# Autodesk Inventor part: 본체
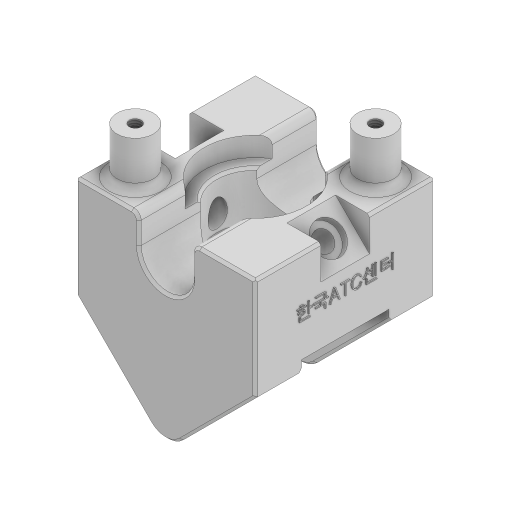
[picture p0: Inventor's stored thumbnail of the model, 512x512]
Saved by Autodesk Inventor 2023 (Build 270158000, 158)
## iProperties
Created: 2025-02
Part Number: 본체
Material: 일반
Document SubType Name: Modeling
Designer: home
Density: 1 g/cm^3
Appearance: 기본값
Author: home
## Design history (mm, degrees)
sketch "스케치1"
  geometry: L1 (-37, 21)-(37, 21); L2 (37, 21)-(37, -21); L3 (-37, -21)-(-37, 21); L4 (-37, 21)-(37, -21); L5 (37, 21)-(-37, -21); L6 (-37, -21)-(0, -58); L7 (0, -58)-(37, -21); 1 further point
  constraints: 14 end point, 2 midpoint, 1 horizontal, 1 parallel, 1 perpendicular, 1 vertical alignment
  dimensions: "d0" = 74 distance of L1.start L1.end; "d2" = 90 deg angle of L7 L6; "d3" = 42 distance of L1.end L2.end
extrude "돌출1" new body sketch "스케치1" stored distance "d4" = 74; taper "d5" = 0 deg
sketch "스케치2"
  geometry: C1 r 21 at (37, 37); C2 r 16 at (37, 37); 1 further point
  constraints: 2 centre point, 2 coincident
  dimensions: "d6" = 42 diameter of C1; "d8" = 32 diameter of C2
extrude "돌출2" cut sketch "스케치2" distance "d9" = 28; taper "d10" = 0 deg
sketch "스케치3"
  geometry: C1 r 16 at (37, 37) reference; C2 r 21 at (37, 37)
  constraints: 1 centre point, 1 coincident
  dimensions: "d11" = 42 diameter of C2
extrude "돌출3" cut sketch "스케치3" distance "d12" = 8; taper "d13" = 0 deg
sketch "스케치4"
  geometry: C1 r 21 at (37, 37) reference; A1 r 7.5 centre (61.749, 61.749) between (66.453, 55.908) and (55.908, 66.453); A2 r 7.5 centre (12.251, 12.251) between (7.547, 18.092) and (18.092, 7.547); A3 r 35 centre (37, 37) between (55.908, 66.453) and (7.547, 18.092); A4 r 35 centre (37, 37) between (18.092, 7.547) and (66.453, 55.908)
  constraints: 8 point on circle, 4 centre point, 1 coincident
  dimensions: "d15" = 15 diameter of A1; "d16" = 15 diameter of A2
extrude "돌출4" join sketch "스케치4" distance "d17" = 19; taper "d18" = 0 deg
sketch "스케치5"
  geometry: L1 (0, -58)-(-37, -21) reference; L2 (-37, -21)-(-37, 21) reference; L3 (-37, 21)-(-21, 21) reference; L4 (-21, 21)-(-21, 13) reference; L5 (-21, 13)-(-16, 13) reference; L6 (-16, 13)-(-16, -7) reference; L7 (-16, -7)-(16, -7) reference; L8 (16, -7)-(16, 13) reference; L9 (16, 13)-(21, 13) reference; L10 (21, 13)-(21, 21) reference; L11 (21, 21)-(37, 21) reference; L12 (37, 21)-(37, -21) reference; L13 (37, -21)-(0, -58) reference; L14 (11, 9)-(11, 41.342); L15 (11, 41.342)-(-11, 41.342); L16 (-11, 41.342)-(-11, 9); L17 (0, 9)-(-11, 9); L18 (0, 9)-(11, 9); A1 r 11 centre (0, 9) between (11, 9) and (-11, 9); 1 further point
  constraints: 10 end point, 2 point on circle, 1 centre point, 1 collinear, 1 perpendicular, 1 tangent, 1 vertical, 1 vertical alignment
  dimensions: "d19" = 22 diameter of A1; "d20" = 12 distance from line of L17.start L3; "d21" = 22 distance of L14.end L15.end
extrude "돌출5" cut sketch "스케치5" extent not by distance; stored distance "d22" = 0; taper "d23" = 0 deg
sketch "스케치6"
  geometry: L1 (0, -58)-(-37, -21) reference; L2 (-37, -21)-(-37, 21) reference; L3 (-37, 21)-(-21, 21) reference; L4 (-21, 21)-(-21, 13) reference; L5 (-21, 13)-(-16, 13) reference; L6 (-16, 13)-(-16, -7) reference; L7 (-16, -7)-(16, -7) reference; L8 (16, -7)-(16, 13) reference; L9 (16, 13)-(21, 13) reference; L10 (21, 13)-(21, 21) reference; L11 (21, 21)-(37, 21) reference; L12 (37, 21)-(37, -21) reference; L13 (37, -21)-(0, -58) reference; L14 (11, 21)-(37, 21) reference; L15 (23, 21)-(37, 7); L16 (37, 21)-(37, -21) reference; L17 (-23, 21)-(-37, 7); 3 further points
  constraints: 4 end point, 4 point on line
  dimensions: "d24" = 14 distance of L11.end L15.start; "d25" = 14 distance of L15.end L11.end; "d26" = 14 distance of L17.start L2.end; "d27" = 14 distance of L17.end L2.end
extrude "돌출6" cut sketch "스케치6" stored distance "d28" = 20; taper "d29" = 0 deg
sketch "스케치8"
  geometry: L1 (0, 0)-(19.799, 0) reference; L2 (9.899, 20)-(19.799, 20) reference; L3 (9.899, 20)-(9.899, 0); 2 further points
  constraints: 2 end point, 2 midpoint
hole "구멍1" sketch "스케치8" at (9.899, 10) diameter "d33" = 8; stored, may be unused: countersink angle "d37" = 90 deg, drill point angle "d39" = 0 deg; dims "d34" = 6, "d35" = 13, "d36" = 3, "d38" = 21
sketch "스케치9"
  geometry: C1 r 7.5 at (0, 0) reference; 1 further point
hole "구멍2" sketch "스케치9" at (0, 0) diameter "d40" = 4.917; stored, may be unused: countersink angle "d44" = 90 deg, drill point angle "d46" = 118 deg; dims "d41" = 12, "d42" = 4, "d43" = 2, "d45" = 14
sketch "스케치10"
  geometry: C1 r 7.5 at (0, 0) reference; 1 further point
hole "구멍3" sketch "스케치10" at (0, 0) diameter "d47" = 4.917; stored, may be unused: countersink angle "d51" = 90 deg, drill point angle "d53" = 118 deg; dims "d48" = 12, "d49" = 4, "d50" = 2, "d52" = 14
sketch "스케치11"
  geometry: L1 (0, 74)-(0, 0) reference; L2 (11.314, 37)-(0, 37); L3 (-7.657, 19)-(67.343, 19); L4 (67.343, 19)-(67.343, 55); L5 (67.343, 55)-(-7.657, 55); L6 (-7.657, 55)-(-7.657, 19)
  constraints: 10 end point, 2 parallel, 1 horizontal, 1 midpoint, 1 perpendicular, 1 other
  dimensions: "d54" = 36 distance of L5.end L3.start; "d55" = 75 distance of L4.end L5.end
extrude "돌출8" cut sketch "스케치11" distance "d56" = 3; taper "d57" = 0 deg
fillet "모깎기1" dims "d58" = 9
fillet "모깎기2" dims "d59" = 9
fillet "모깎기3" dims "d60" = 3
chamfer "모따기1" distance "d61" = 1; stored, may be unused: second distance "d62" = 2, angle "d63" = 45 deg
fillet "모깎기4" dims "d64" = 3
chamfer "모따기2" distance "d65" = 1; stored, may be unused: second distance "d66" = 2, angle "d67" = 45 deg
chamfer "모따기3" distance "d68" = 1; stored, may be unused: second distance "d69" = 2, angle "d70" = 45 deg
chamfer "모따기4" distance "d71" = 1; stored, may be unused: second distance "d72" = 2, angle "d73" = 45 deg
chamfer "모따기5" distance "d74" = 1; stored, may be unused: second distance "d75" = 2, angle "d76" = 45 deg
chamfer "모따기6" distance "d77" = 1; stored, may be unused: second distance "d78" = 2, angle "d79" = 45 deg
chamfer "모따기7" distance "d80" = 1; stored, may be unused: second distance "d81" = 2, angle "d82" = 45 deg
chamfer "모따기8" distance "d83" = 1; stored, may be unused: second distance "d84" = 2, angle "d85" = 45 deg
chamfer "모따기9" distance "d86" = 1; stored, may be unused: second distance "d87" = 2, angle "d88" = 45 deg
sketch "스케치12"
  geometry: L1 (42.249, 33)-(27.249, 33) reference; L2 (47, -27.586)-(47, 13) reference; 2 further points
  constraints: 1 other
  dimensions: "d89" = 40 distance from line of L1 point (10, -7); "d90" = 37 distance from line of point (10, -7) L2
feature "엠보싱1" sketch "스케치12" dims "d0" = 74, "d2" = 90 deg, "d3" = 42, "d91" = 0.5, "d92" = 0
node "솔리드1"
mirror "미러2"
mirror "미러3"
node "절단 모서리 투영1"
node "절단 모서리 투영2"
feature "A9D066F2-1C7D-4E18-AEED-F7BC21143FA4" dims "d33" = 8, "d34" = 6, "d35" = 13, "d36" = 3, "d37" = 90 deg, "d38" = 21, "d39" = 0
